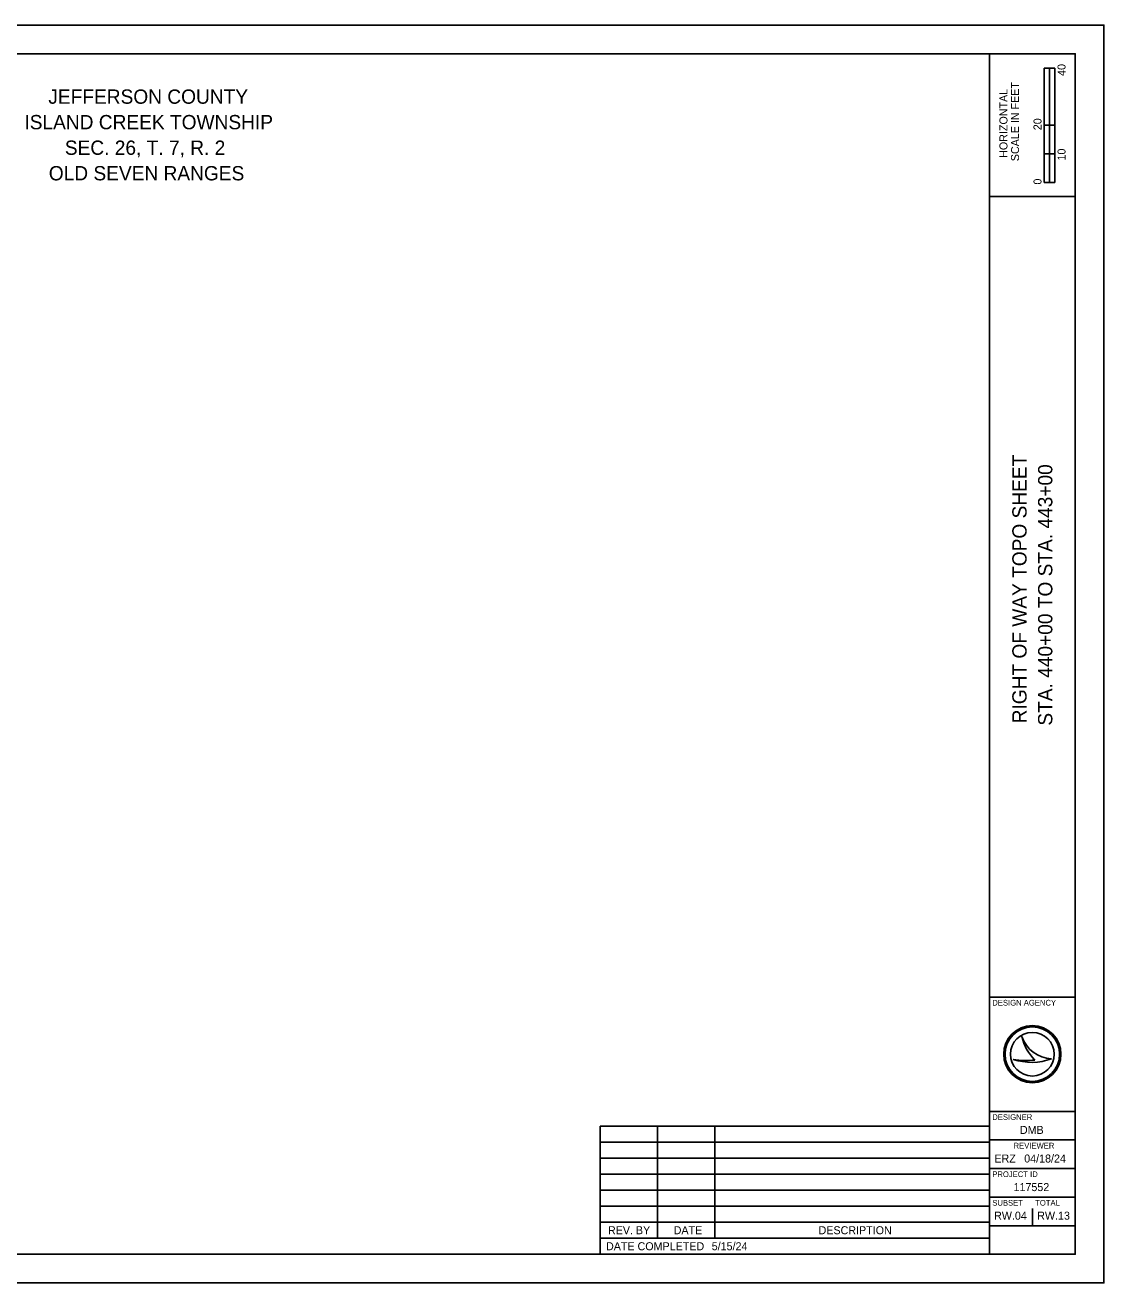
# Model space of a CAD drawing. Extents: x -49 to 1155, y -187 to 440.
# Drawn here: x 302.8 to 680, y 0 to 440 of the extents above; entities that cross this region are included whole.
import ezdxf

# ---------------------------------------------------------------- set-up
doc = ezdxf.new("R2010")
doc.units = 0
for name, color, linetype in [('_CIVIL_CONSTRUCTION', 7, 'Continuous'), ('CM_Corridor_Final', 7, 'Continuous'), ('CM_Corridor_Range_Final', 7, 'Continuous'), ('MD_P_ACIC_B', 7, 'Continuous')]:
    doc.layers.add(name, color=color, linetype=linetype)

msp = doc.modelspace()

# ---------------------------------------------------------------- linework, layer by layer
at = {"layer": '_CIVIL_CONSTRUCTION'}
msp.add_lwpolyline([(0, 0), (680, 0), (680, 440), (0, 440)], close=True, dxfattribs=at)
at = {"layer": 'CM_Corridor_Final'}
for p, q in [((659.13, 385), (659.13, 425)), ((662.88, 425), (659.13, 425)), ((659.13, 405), (659.13, 425)), ((659.13, 425), (661, 425)), ((661, 425), (661.02, 425)), ((661.02, 425), (661.02, 405)), ((662.88, 425), (662.88, 385)), ((661.02, 405), (659.13, 405)), ((662.87, 405), (661, 405)), ((661, 405), (661, 395)), ((662.87, 395), (662.87, 405)), ((661, 395), (659.13, 395)), ((659.13, 395), (659.13, 385)), ((661, 385), (661, 395)), ((661, 395), (662.87, 395)), ((662.88, 385), (659.13, 385)), ((659.13, 385), (661, 385)), ((651.35, 86.19), (651.35, 86.19)), ((655, 80), (655, 80)), ((648.34, 78.19), (648.34, 78.19)), ((661.75, 78.37), (661.75, 78.37)), ((655, 20), (655, 26))]:
    msp.add_line(p, q, dxfattribs=at)
for radius in [10, 9.54, 9.54, 7.64]:
    msp.add_circle((655, 80), radius, dxfattribs=at)
for centre, radius, start, end in [((662.32, 89.95), 11.6, 198.9257, 198.9319), ((666.93, 89.4), 15.91, 191.6379, 191.6421), ((662.32, 89.95), 11.6, 198.9319, 267.1657), ((666.93, 89.4), 15.91, 191.6421, 226.0947), ((654.79, 97.4), 20.26, 251.4576, 290.0832), ((652.96, 103.09), 25.32, 259.4964, 259.4995), ((654.79, 97.4), 20.26, 251.4527, 251.4576), ((652.96, 103.09), 25.32, 259.4995, 276.6672)]:
    msp.add_arc(centre, radius, start, end, dxfattribs=at)
at = {"layer": 'CM_Corridor_Range_Final'}
for p, q in [((640, 10), (640, 430)), ((640, 380), (670, 380)), ((640, 100), (670, 100)), ((640, 60), (670, 60)), ((640, 50), (670, 50)), ((640, 40), (670, 40)), ((640, 30), (670, 30)), ((640, 20), (670, 20))]:
    msp.add_line(p, q, dxfattribs=at)
msp.add_lwpolyline([(30, 430), (670, 430), (670, 10), (30, 10)], close=True, dxfattribs=at)
at = {"layer": 'MD_P_ACIC_B'}
for p, q in [((503.93, 54.8), (503.93, 10)), ((503.93, 54.8), (640, 54.8)), ((523.93, 54.8), (523.93, 15.6)), ((543.93, 54.8), (543.93, 15.6)), ((503.93, 49.2), (640, 49.2)), ((503.93, 43.6), (640, 43.6)), ((503.93, 38), (640, 38)), ((503.93, 32.4), (640, 32.4)), ((503.93, 26.8), (640, 26.8)), ((503.93, 21.2), (640, 21.2)), ((503.93, 15.6), (640, 15.6)), ((640, 10), (640, 10))]:
    msp.add_line(p, q, dxfattribs=at)

# ---------------------------------------------------------------- texts
at = {"layer": 'CM_Corridor_Final'}
for s, height, p in [('40', 2.8, (666.61, 422.25)), ('SCALE IN FEET', 2.8, (650.35, 392.41)), ('HORIZONTAL', 2.8, (646.3, 393.58)), ('20', 2.8, (658.21, 403.25)), ('10', 2.8, (666.61, 392.65)), ('0', 2.8, (658.21, 384.23)), ('RIGHT OF WAY TOPO SHEET', 5, (653, 195.74)), ('STA. 440+00 TO STA. 443+00', 5, (662, 194.94))]:
    msp.add_text(s, height=height, rotation=90, dxfattribs=at).set_placement(p)
for s, height, p in [('             JEFFERSON COUNTY             ', 5, (286.77, 412.5)), ('           ISLAND CREEK TOWNSHIP          ', 5, (282.12, 403.57)), ('            SEC. 26, T. 7, R. 2           ', 5, (294.4, 394.63)), ('             OLD SEVEN RANGES             ', 5, (286.93, 385.7)), ('DESIGN AGENCY', 2, (641, 97)), ('DESIGNER', 2, (641, 57)), ('DMB', 2.8, (650.65, 52.1)), ('REVIEWER', 2, (648.44, 47)), ('ERZ', 2.8, (641.74, 42.1)), ('04/18/24', 2.8, (652.16, 42.1)), ('PROJECT ID', 2, (641, 37)), ('117552', 2.8, (648.42, 32.1)), ('SUBSET', 2, (641, 27)), ('TOTAL', 2, (656, 27)), ('RW.04', 2.8, (641.63, 22.1)), ('RW.13', 2.8, (656.7, 22.1))]:
    msp.add_text(s, height=height, dxfattribs=at).set_placement(p)
at = {"layer": 'MD_P_ACIC_B'}
for s, p in [('REV. BY', (506.61, 17)), ('DATE', (529.59, 17)), ('DESCRIPTION', (580.25, 17)), ('DATE COMPLETED', (505.93, 11.4)), ('5/15/24                            ', (542.89, 11.4))]:
    msp.add_text(s, height=2.8, dxfattribs=at).set_placement(p)

doc.saveas('drawing.dxf')
